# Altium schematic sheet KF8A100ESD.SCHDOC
size A4
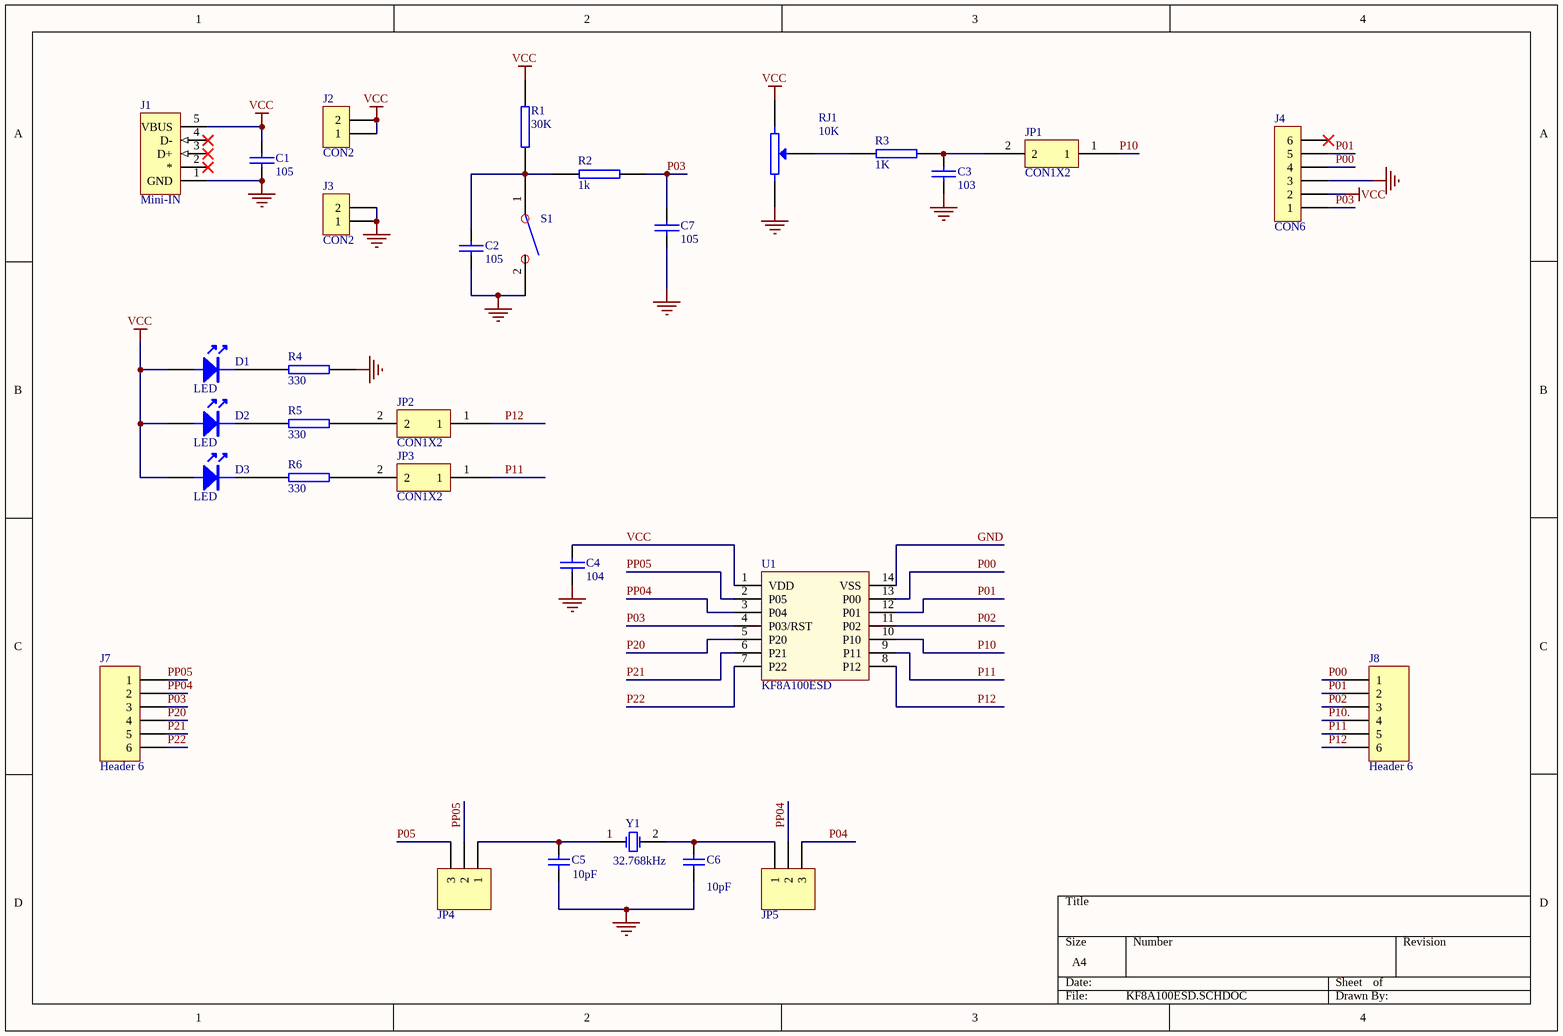
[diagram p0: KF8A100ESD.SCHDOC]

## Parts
C1  105  [0805]
C2  105  [0805]
C3  103  [0805]
C4  104  [0805]
C5  value 10pF  [0805]
C6  value 10pF  [0805]
C7  105  [0805]
D1  LED  [LED0805]
D2  LED  [LED0805]
D3  LED  [LED0805]
J1  Mini-IN  [MINI B USB]
J2  CON2  [SIP2]
J3  CON2  [SIP2]
J4  CON6  [ICSP887]
J7  Header 6  [HDR1X6]
J8  Header 6  [HDR1X6]
JP1  CON1X2  [SIP2]
JP2  CON1X2  [SIP2]
JP3  CON1X2  [SIP2]
JP4  (no value)  [HDR1X3]
JP5  (no value)  [HDR1X3]
R1  30K  [0805]
R2  1k  [0805]
R3  1K  [0805]
R4  330  [0805]
R5  330  [0805]
R6  330  [0805]
RJ1  10K  [VR5H]
S1  (no value)  [SW_SOP]
U1  KF8A100ESD
Y1  32.768kHz  [BCY-W2/D3.1]

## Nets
GND: C1.2 C2.2 C3.2 C4.2 C5.1 C6.1 C7.2 J1.1(GND) J3.1 J3.2 J4.3 R4.1 RJ1.2 S1.2 U1.14(VSS)
VCC: C1.1 C4.1 D1.A D2.A D3.A J1.5(VBUS) J2.1 J2.2 J4.2 R1.2 RJ1.1 U1.1(VDD)
P00: J4.4 J8.1 U1.13(P00)
P01: J4.5 J8.2 U1.12(P01)
P02: J8.3 U1.11(P02)
P03: C7.1 J4.1 J7.3 R2.1 U1.4(P03/RST)
P04: JP5.3
P05: JP4.3
P10: JP1.1 U1.10(P10)
P10.: J8.4
P11: J8.5 JP3.1 U1.9(P11)
P12: J8.6 JP2.1 U1.8(P12)
P20: J7.4 U1.5(P20)
P21: J7.5 U1.6(P21)
P22: J7.6 U1.7(P22)
PP04: J7.2 JP5.2 U1.3(P04)
PP05: J7.1 JP4.2 U1.2(P05)
NetC2_1: C2.1 R1.1 R2.2 S1.1
NetC3_1: C3.1 JP1.2 R3.1
NetC5_2: C5.2 JP4.1 Y1.1(OSC1)
NetC6_2: C6.2 JP5.1 Y1.2(OSC2)
NetD1_K: D1.K R4.2
NetD2_K: D2.K R5.2
NetD3_K: D3.K R6.2
NetJP2_2: JP2.2 R5.1
NetJP3_2: JP3.2 R6.1
NetR3_2: R3.2 RJ1.3(W)

Not connected (* = marked no-connect by the designer): J1 2(*)* 3(D+)* 4(D-)*; J4 6*

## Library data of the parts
C1-C4 C7 = CAP: Capacitor
C5 C6 = Cap: Capacitor
J1 = USB-5: USB 1.1, Right Angle, Thru-Hole, Reverse Type, Receptacle, 4 Position, Black
J2 J3 = CON2: Connector
J4 = CON6: Connector
J7 J8 = Header 6: Header, 6-Pin
JP1-JP3 = CON1X2: J?
JP4 JP5 = Header 3: Header, 3-Pin
R1-R6 = RES2
RJ1 = POT2: Potentiometer
S1 = KEY_X
Y1 = XTAL: Crystal Oscillator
